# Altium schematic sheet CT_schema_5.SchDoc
size 411 x 381 mm
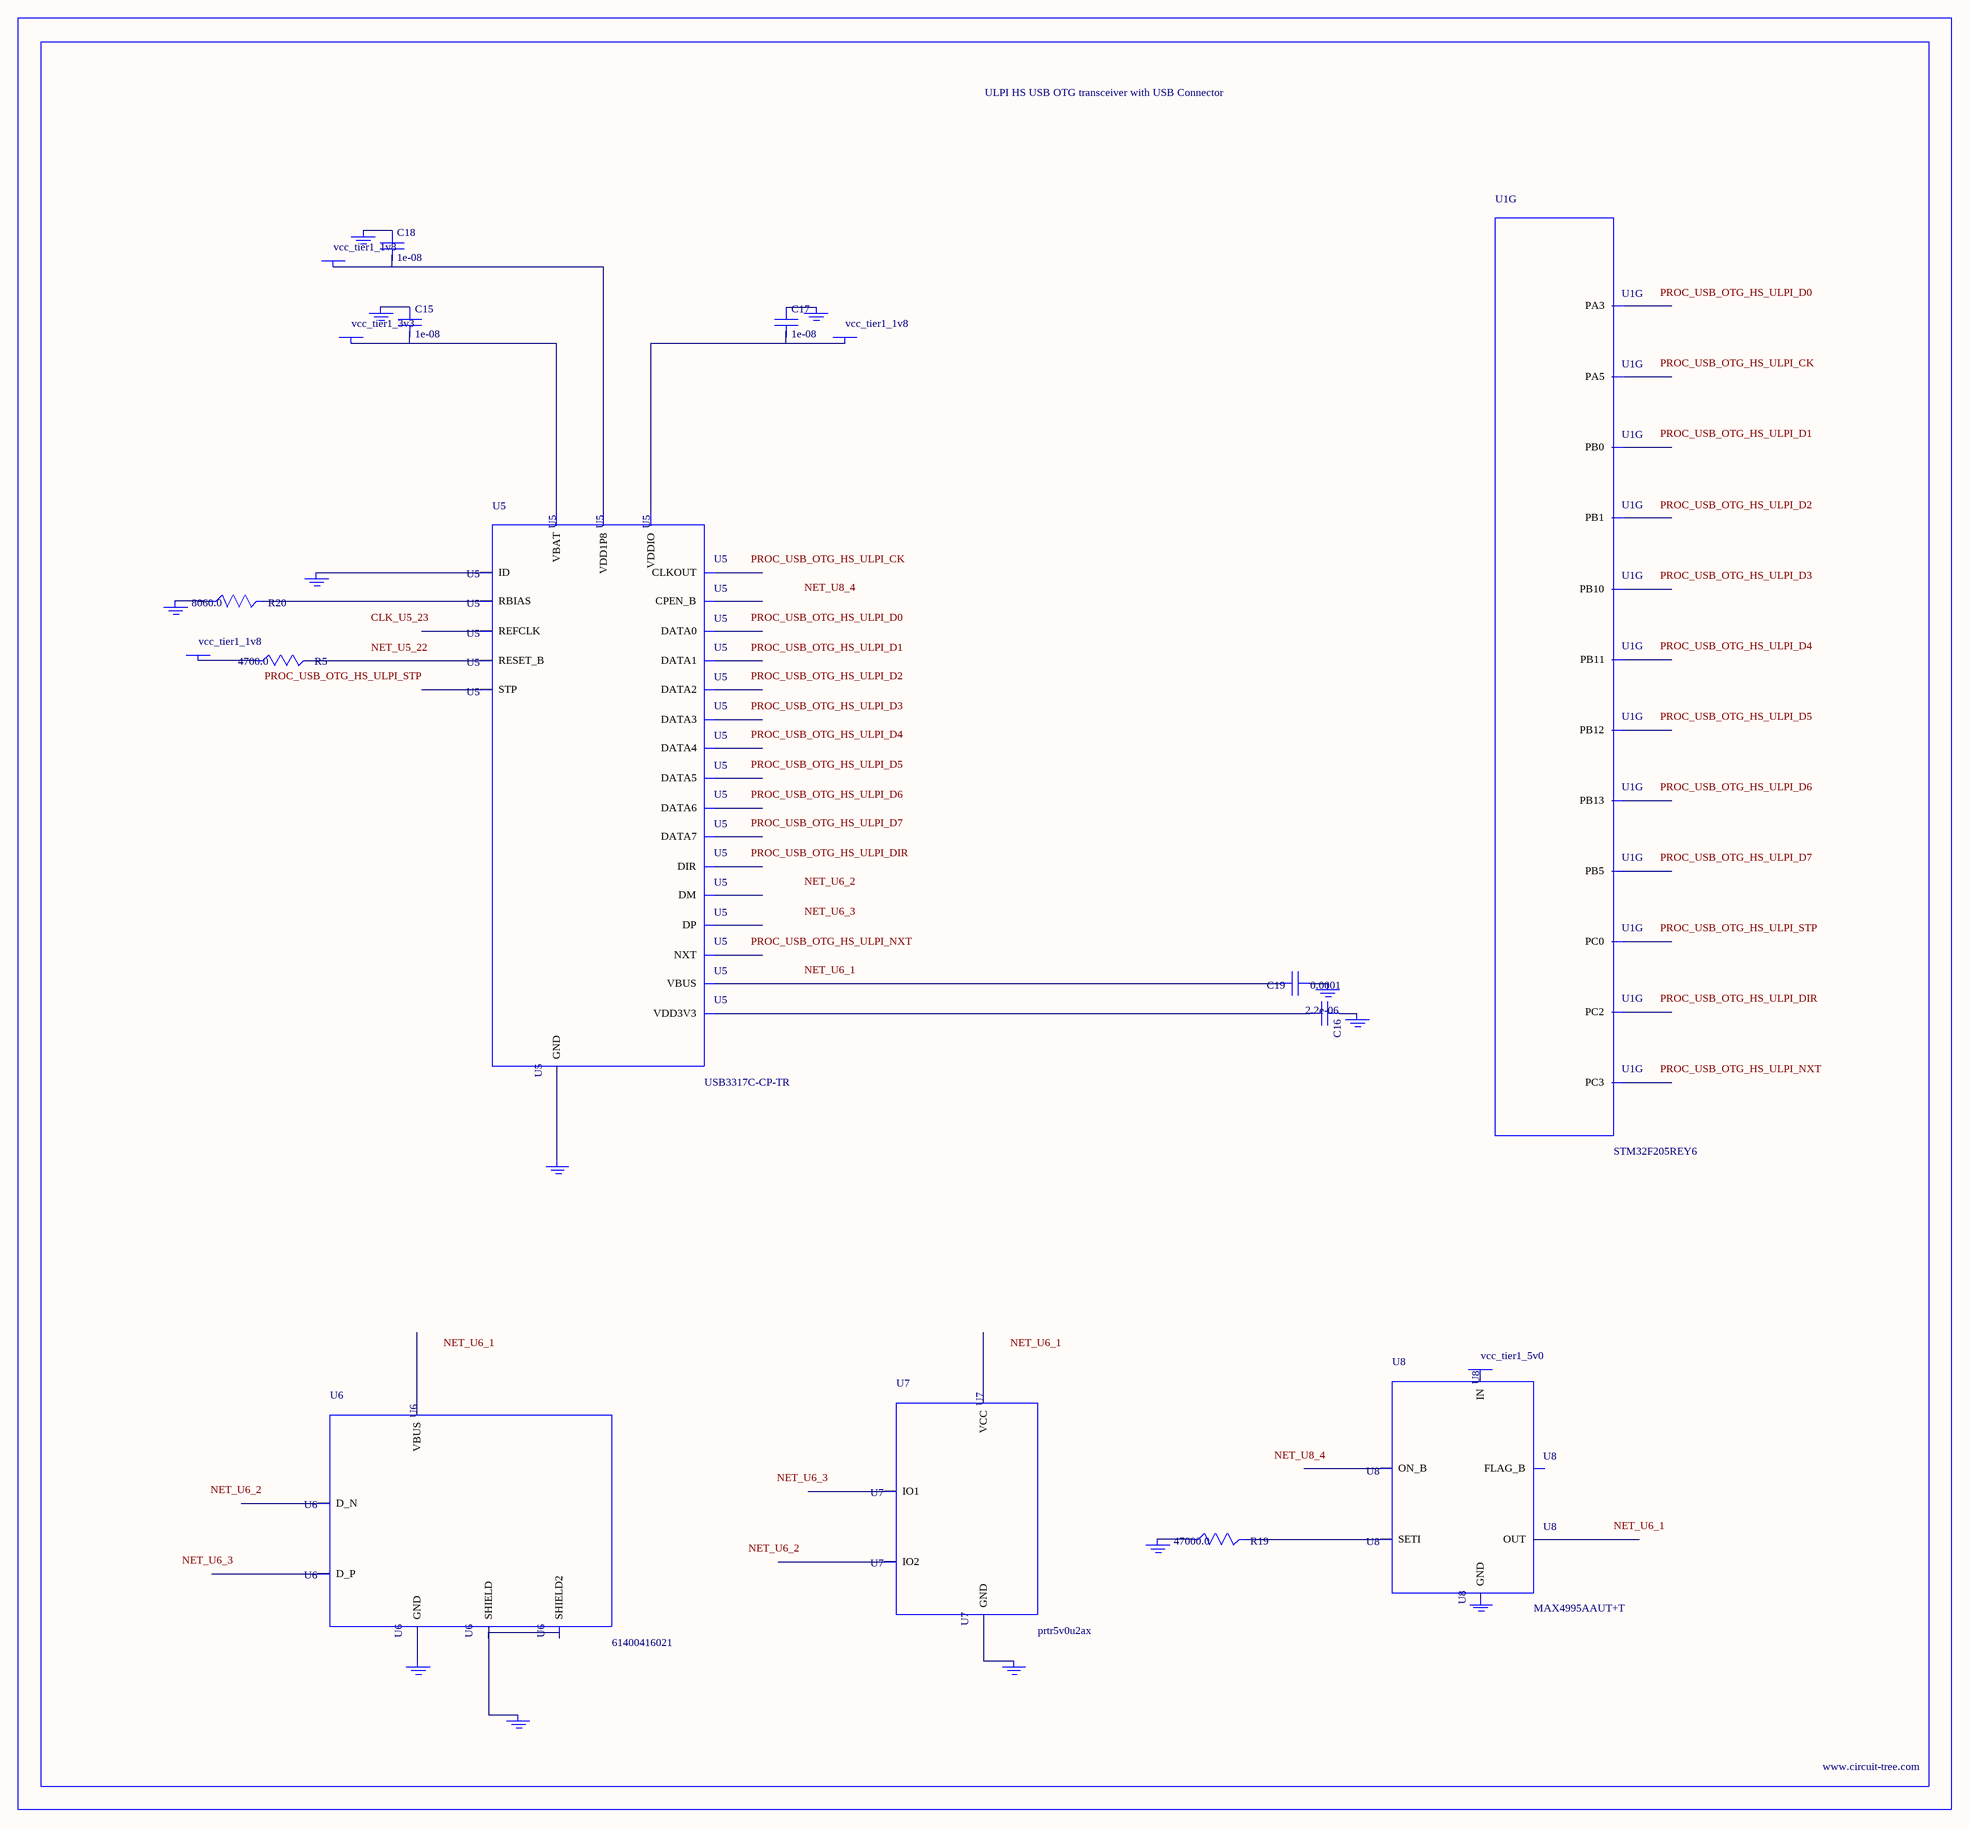
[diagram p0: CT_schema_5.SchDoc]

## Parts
BORDER4  (no value)
C15  1e-08  [C0402]
C16  2.2e-06  [C0603]
C17  1e-08  [C0402]
C18  1e-08  [C0402]
C19  0.0001  [R0603]
GND_INSTANCE_4_0  (no value)
GND_INSTANCE_4_1  (no value)
GND_INSTANCE_4_2  (no value)
GND_INSTANCE_4_3  (no value)
GND_INSTANCE_4_4  (no value)
GND_INSTANCE_4_5  (no value)
GND_INSTANCE_4_6  (no value)
GND_INSTANCE_4_7  (no value)
GND_INSTANCE_4_8  (no value)
GND_INSTANCE_4_9  (no value)
GND_INSTANCE_4_10  (no value)
GND_INSTANCE_4_11  (no value)
GND_INSTANCE_4_12  (no value)
POWER_INSTANCE_4_0  vcc_tier1_3v3
POWER_INSTANCE_4_1  vcc_tier1_1v8
POWER_INSTANCE_4_2  vcc_tier1_1v8
POWER_INSTANCE_4_3  vcc_tier1_1v8
POWER_INSTANCE_4_4  vcc_tier1_5v0
R5  4700.0  [R0603]
R19  47000.0  [R0603]
R20  8060.0  [R0603]
U1  STM32F205REY6  [WLCSP66]  (part G of 7)
U5  USB3317C-CP-TR  [QFN-24]
U6  61400416021  [USB-A-H]
U7  prtr5v0u2ax  [SOT143B]
U8  MAX4995AAUT+T  [SOT-23-6]

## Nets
NetC15_1: C15.1 GND_INSTANCE_4_2.0(GND)
NetC15_2: C15.2 POWER_INSTANCE_4_0.0(PWR) U5.3(VBAT)
NetC16_1: C16.1 GND_INSTANCE_4_3.0(GND)
NetC16_2: C16.2 U5.4(VDD3V3)
NetC17_1: C17.1 GND_INSTANCE_4_4.0(GND)
NetC17_2: C17.2 POWER_INSTANCE_4_1.0(PWR) U5.17(VDDIO)
NetC18_1: C18.1 GND_INSTANCE_4_5.0(GND)
NetC18_2: C18.2 POWER_INSTANCE_4_2.0(PWR) U5.21(VDD1P8)
NetC19_1: C19.1 GND_INSTANCE_4_1.0(GND)
NetC19_2: C19.2 U5.2(VBUS)
NetGND_INSTANCE_4_0_0: GND_INSTANCE_4_0.0(GND) U5.1(ID)
NetGND_INSTANCE_4_6_0: GND_INSTANCE_4_6.0(GND) R20.1
NetGND_INSTANCE_4_7_0: GND_INSTANCE_4_7.0(GND) U5.25(GND)
NetGND_INSTANCE_4_8_0: GND_INSTANCE_4_8.0(GND) U6.5(SHIELD) U6.6(SHIELD2)
NetGND_INSTANCE_4_9_0: GND_INSTANCE_4_9.0(GND) U6.4(GND)
NetGND_INSTANCE_4_10_0: GND_INSTANCE_4_10.0(GND) U7.1(GND)
NetGND_INSTANCE_4_11_0: GND_INSTANCE_4_11.0(GND) R19.1
NetPOWER_INSTANCE_4_3_0: POWER_INSTANCE_4_3.0(PWR) R5.1
NetR5_2: R5.2 U5.22(RESET_B)
NetR19_2: R19.2 U8.3(SETI)
NetR20_2: R20.2 U5.24(RBIAS)

Not connected (* = marked no-connect by the designer): GND_INSTANCE_4_12 0(GND); POWER_INSTANCE_4_4 0(PWR); U1 A5(PB5) D7(PC2) G7(PA3) G8(PC3) G9(PC0) H2(PB13) H3(PB10) H6(PA5) J1(PB12) J2(PB11) J5(PB1) J6(PB0); U5 5(DM) 6(DP) 7(CPEN_B) 8(DATA7) 9(DATA6) 10(DATA5) 11(DATA4) 12(CLKOUT) 13(DATA3) 14(DATA2) 15(DATA1) 16(DATA0) 18(NXT) 19(DIR) 20(STP) 23(REFCLK); U6 1(VBUS) 2(D_N) 3(D_P); U7 2(IO1) 3(IO2) 4(VCC); U8 1(OUT) 2(GND) 4(ON_B) 5(IN) 6(FLAG_B)

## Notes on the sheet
- Labels drawn without touching a wire or pin: CLK_U5_23, NET_U5_22, NET_U6_1, NET_U6_2, NET_U6_3, NET_U8_4, PROC_USB_OTG_HS_ULPI_CK, PROC_USB_OTG_HS_ULPI_D0, PROC_USB_OTG_HS_ULPI_D1, PROC_USB_OTG_HS_ULPI_D2, PROC_USB_OTG_HS_ULPI_D3, PROC_USB_OTG_HS_ULPI_D4, PROC_USB_OTG_HS_ULPI_D5, PROC_USB_OTG_HS_ULPI_D6, PROC_USB_OTG_HS_ULPI_D7, PROC_USB_OTG_HS_ULPI_DIR, PROC_USB_OTG_HS_ULPI_NXT, PROC_USB_OTG_HS_ULPI_STP

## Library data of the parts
BORDER4 = BORDER_PAGE4
C15 C17 C18 = C0402C103K3RAC
C16 = C0603C225K8RACTU
C19 = C19
GND_INSTANCE_4_0-GND_INSTANCE_4_12 = GND
POWER_INSTANCE_4_0-POWER_INSTANCE_4_4 = PWR
R5 = RC0603JR-074K7L
R19 = RC0603JR-0747KL
R20 = ERJ-3EKF8061V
